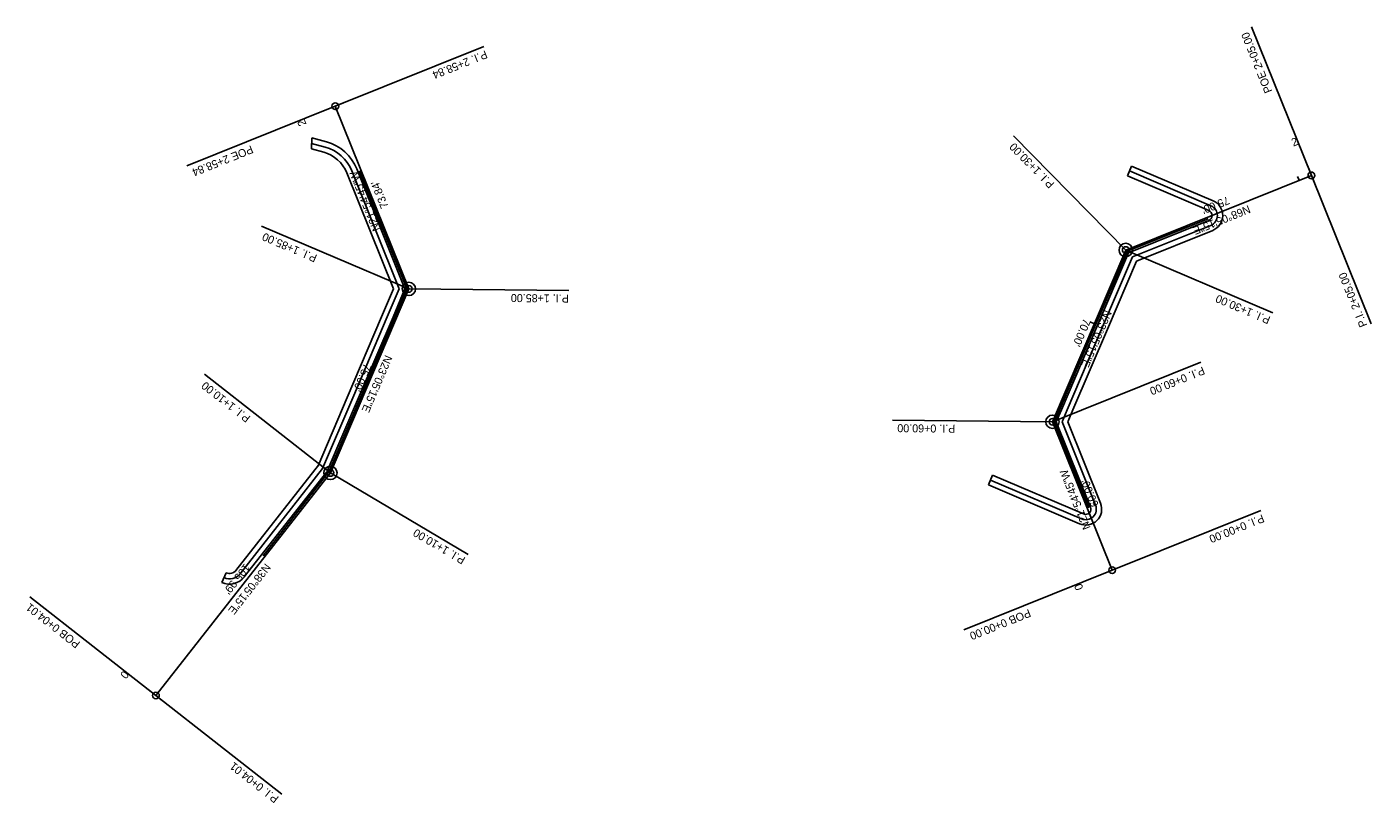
# Model space of a CAD drawing. Extents: x 653228 to 653731, y 408300 to 408591.
import ezdxf

# ---------------------------------------------------------------- set-up
doc = ezdxf.new("R2010")
doc.units = 0
for name, color, linetype in [('R_Horz Alg Wall', 7, 'Continuous'), ('R_Horz Alg Wall Control', 7, 'Continuous'), ('R_Horz Alg Wall Station', 7, 'Continuous'), ('R_No Plot', 7, 'Continuous'), ('R_Wall', 7, 'Continuous'), ('R_Water', 7, 'Continuous')]:
    doc.layers.add(name, color=color, linetype=linetype)

msp = doc.modelspace()

# ---------------------------------------------------------------- linework, layer by layer
at = {"layer": 'R_Horz Alg Wall'}
for p, q in [((653370.72, 408492.94), (653343.16, 408561.44)), ((653639.37, 408507.54), (653708.95, 408535.52)), ((653611.92, 408443.14), (653639.37, 408507.54)), ((653341.3, 408423.94), (653370.72, 408492.94)), ((653634.31, 408387.48), (653611.92, 408443.14)), ((653275.93, 408340.52), (653341.3, 408423.94))]:
    msp.add_line(p, q, dxfattribs=at)
for centre in [(653343.16, 408561.44), (653708.95, 408535.52), (653639.37, 408507.54), (653370.72, 408492.94), (653611.92, 408443.14), (653341.3, 408423.94), (653634.31, 408387.48), (653275.93, 408340.52)]:
    msp.add_circle(centre, 1.25, dxfattribs=at)
at = {"layer": 'R_Horz Alg Wall Control'}
for points in [[(653708.95, 408535.52), (653686.56, 408591.19)], [(653343.16, 408561.44), (653398.83, 408583.83)], [(653343.16, 408561.44), (653287.49, 408539.05)], [(653639.37, 408507.54), (653597.38, 408550.39)], [(653708.95, 408535.52), (653731.35, 408479.86)], [(653370.72, 408492.94), (653315.52, 408516.46)], [(653639.37, 408507.54), (653694.57, 408484.01)], [(653370.72, 408492.94), (653430.71, 408492.32)], [(653611.92, 408443.14), (653667.59, 408465.53)], [(653341.3, 408423.94), (653294.08, 408460.95)], [(653611.92, 408443.14), (653551.93, 408443.76)], [(653341.3, 408423.94), (653392.96, 408393.41)], [(653634.31, 408387.48), (653689.98, 408409.87)], [(653634.31, 408387.48), (653578.65, 408365.09)], [(653275.93, 408340.52), (653228.7, 408377.54)], [(653275.93, 408340.52), (653323.15, 408303.51)]]:
    msp.add_lwpolyline(points, dxfattribs=at)
for centre in [(653639.37, 408507.54), (653370.72, 408492.94), (653611.92, 408443.14), (653341.3, 408423.94)]:
    msp.add_circle(centre, 2.5, dxfattribs=at)
at = {"layer": 'R_Horz Alg Wall Station'}
for points in [[(653340.38, 408560.32), (653345.94, 408562.56)], [(653703.76, 408535.05), (653704.32, 408533.66)], [(653707.83, 408538.31), (653710.07, 408532.74)], [(653363.73, 408506.29), (653365.12, 408506.85)], [(653626.23, 408480.53), (653627.61, 408479.94)], [(653333.96, 408417), (653335.14, 408416.07)], [(653631.53, 408386.36), (653637.1, 408388.6)], [(653273.56, 408342.37), (653278.29, 408338.67)]]:
    msp.add_lwpolyline(points, dxfattribs=at)
at = {"layer": 'R_Wall'}
for p, q in [((653370.1, 408492.69), (653352.18, 408537.22)), ((653639.62, 408506.92), (653670.24, 408519.23)), ((653627.48, 408477.93), (653639.99, 408507.27)), ((653365.5, 408482.41), (653370.1, 408493.2)), ((653352.59, 408452.13), (653365.5, 408482.41)), ((653614.57, 408447.64), (653627.48, 408477.93)), ((653340.69, 408424.2), (653352.59, 408452.13)), ((653612.54, 408442.88), (653614.57, 408447.64)), ((653625.6, 408410.92), (653612.54, 408443.39)), ((653316.11, 408392.87), (653340.78, 408424.35))]:
    msp.add_line(p, q, dxfattribs=at)
at = {"layer": 'R_Water'}
for p, q in [((653334.33, 408549.53), (653339.85, 408548.04)), ((653334.26, 408545.41), (653338.81, 408544.18)), ((653334.27, 408547.48), (653339.33, 408546.11)), ((653640.01, 408535.32), (653641.58, 408539)), ((653672.09, 408525.99), (653641.58, 408539)), ((653364.94, 408492.99), (653347.45, 408536.49)), ((653367.11, 408492.97), (653349.3, 408537.24)), ((653369.27, 408492.95), (653351.16, 408537.98)), ((653670.52, 408522.31), (653640.01, 408535.32)), ((653671.31, 408524.15), (653640.79, 408537.16)), ((653640.38, 408506.5), (653670.49, 408518.61)), ((653641.9, 408504.96), (653671.23, 408516.76)), ((653643.41, 408503.41), (653671.98, 408514.9)), ((653640.38, 408506.5), (653628.2, 408477.91)), ((653630.35, 408477.88), (653641.9, 408504.96)), ((653632.51, 408477.84), (653643.41, 408503.41)), ((653360.47, 408482.5), (653364.94, 408492.99)), ((653362.63, 408482.46), (653367.11, 408492.97)), ((653364.78, 408482.42), (653369.27, 408492.95)), ((653347.56, 408452.21), (653360.47, 408482.5)), ((653349.72, 408452.18), (653362.63, 408482.46)), ((653351.87, 408452.14), (653364.78, 408482.42)), ((653628.2, 408477.91), (653615.29, 408447.63)), ((653617.44, 408447.59), (653630.35, 408477.88)), ((653619.6, 408447.56), (653632.51, 408477.84)), ((653336.67, 408426.68), (653347.56, 408452.21)), ((653338.41, 408425.65), (653349.72, 408452.18)), ((653340.15, 408424.63), (653351.87, 408452.14)), ((653615.29, 408447.63), (653613.37, 408443.13)), ((653613.37, 408443.13), (653626.22, 408411.17)), ((653615.53, 408443.11), (653617.44, 408447.59)), ((653628.08, 408411.91), (653615.53, 408443.11)), ((653617.7, 408443.08), (653619.6, 408447.56)), ((653629.93, 408412.66), (653617.7, 408443.08)), ((653305.91, 408387.42), (653336.84, 408426.89)), ((653307.48, 408386.19), (653338.41, 408425.65)), ((653309.05, 408384.96), (653339.98, 408424.42)), ((653587.9, 408419.45), (653589.47, 408423.13)), ((653623.58, 408408.58), (653589.47, 408423.13)), ((653622.01, 408404.9), (653587.9, 408419.45)), ((653622.8, 408406.74), (653588.68, 408421.29)), ((653302.3, 408386.54), (653300.65, 408382.9))]:
    msp.add_line(p, q, dxfattribs=at)
msp.add_lwpolyline([(653334.26, 408545.41), (653334.33, 408549.53)], dxfattribs=at)
for centre, radius, start, end in [((653335.39, 408531.64), 13, 21.9125, 74.7536), ((653335.39, 408531.64), 15, 21.9125, 74.7536), ((653335.39, 408531.64), 17, 21.9125, 74.7536), ((653669.74, 408520.47), 4, 291.9125, 66.9125), ((653669.74, 408520.47), 6, 291.9125, 66.9125), ((653669.74, 408520.47), 2, 291.9125, 66.9125), ((653624.37, 408410.42), 6, 246.9125, 21.9125), ((653624.37, 408410.42), 4, 246.9125, 21.9125), ((653624.37, 408410.42), 2, 246.9125, 21.9125), ((653303.55, 408389.27), 7, 245.5323, 321.9125), ((653303.55, 408389.27), 5, 245.5323, 321.9125), ((653303.55, 408389.27), 3, 245.5323, 321.9125)]:
    msp.add_arc(centre, radius, start, end, dxfattribs=at)

# ---------------------------------------------------------------- texts
at = {"layer": 'R_Horz Alg Wall Control'}
for s, rotation, p in [('POE 2+05.00', 111.9125, (653694.38, 408567.07)), ('P.I. 2+58.84', 201.9125, (653399.39, 408582.44)), ('POE 2+58.84', 201.9125, (653311.61, 408546.86)), ('P.I. 1+30.00', 134.4125, (653612.85, 408532.46)), ('P.I. 1+85.00', 156.9125, (653336.58, 408505.59)), ('P.I. 2+05.00', 111.9125, (653729.95, 408479.3)), ('P.I. 1+85.00', 179.4125, (653430.7, 408490.82)), ('P.I. 1+30.00', 156.9125, (653693.88, 408482.4)), ('P.I. 0+60.00', 201.9125, (653668.24, 408463.91)), ('P.I. 1+10.00', 141.9125, (653311.6, 408445)), ('P.I. 0+60.00', 179.4125, (653575.54, 408442.02)), ('P.I. 0+00.00', 201.9125, (653690.54, 408408.48)), ('P.I. 1+10.00', 149.4125, (653392.19, 408392.12)), ('POB 0+04.01', 141.9125, (653247.78, 408360.36)), ('POB 0+00.00', 201.9125, (653603.06, 408373.02)), ('P.I. 0+04.01', 141.9125, (653322.22, 408302.33))]:
    msp.add_text(s, height=3, rotation=rotation, dxfattribs=at).set_placement(p)
at = {"layer": 'R_Horz Alg Wall Station'}
for s, rotation, p in [('2', 111.9125, (653332.41, 408554.66)), ('2', 21.9125, (653702.18, 408546.27)), ('0', 111.9125, (653623.57, 408380.7)), ('0', 51.9125, (653264.69, 408346.45))]:
    msp.add_text(s, height=3, rotation=rotation, dxfattribs=at).set_placement(p)
at = {"layer": 'R_No Plot'}
for s, rotation, p in [('N21%%d54\'45"W', 111.9125, (653360.1, 408515.31)), ("73.84'", 111.9125, (653363.15, 408523.8)), ('N68%%d05\'15"E', 201.9125, (653685.35, 408524.41)), ("75.00'", 201.9125, (653677.55, 408527.74)), ('N23%%d05\'15"E', 246.9125, (653631.52, 408485.29)), ("70.00'", 246.9125, (653623.65, 408482.12)), ('N23%%d05\'15"E', 246.9125, (653361.88, 408468.39)), ("75.00'", 246.9125, (653354.01, 408465.22)), ('N21%%d54\'45"W', 111.9125, (653626.28, 408403.43)), ("60.00'", 111.9125, (653629.33, 408411.93)), ("105.99'", 231.9125, (653309.13, 408390.19)), ('N38%%d05\'15"E', 231.9125, (653316.86, 408390.32))]:
    msp.add_text(s, height=3, rotation=rotation, dxfattribs=at).set_placement(p)

doc.saveas('drawing.dxf')
